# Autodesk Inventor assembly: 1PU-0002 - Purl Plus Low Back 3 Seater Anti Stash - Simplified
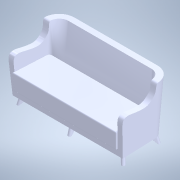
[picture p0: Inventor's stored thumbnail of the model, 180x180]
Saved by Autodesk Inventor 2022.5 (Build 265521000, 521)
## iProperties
Created: 2025-09
Part Number: 1PU-0002 - Purl Plus Low Back 3 Seater Anti Stash - Simplified
Description: STEP AP214
Document SubType Name: Assembly
Designer: Mark.Glazzard
Title: 1PU-0002 - Purl Plus Low Back 3 Seater Anti Stash (Upholstered).STEP
Revision Number: ANY
Sending System: SolidWorks 2025
Preprocessor: SwSTEP 2.0
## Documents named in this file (5)
- S:\DRAWINGS\DRAWING OFFICE ONLY\WIP\1306 Purl 3-Seater\1PU-0002 - Purl Plus Low Back Anti Stash 3 Seater\1PU-0002 SIMPLIFIED\1PU-0002 - Purl Plus Low Back 3 Seater Anti Stash - Simplified.iam
- S:\DRAWINGS\DRAWING OFFICE ONLY\WIP\1306 Purl 3-Seater\1PU-0002 - Purl Plus Low Back Anti Stash 3 Seater\1PU-0002 STEP SAT DWG\1PU-0002 - BEECH FEET.ipt
- S:\DRAWINGS\DRAWING OFFICE ONLY\WIP\1306 Purl 3-Seater\1PU-0002 - Purl Plus Low Back Anti Stash 3 Seater\1PU-0002 STEP SAT DWG\1PU-0002 - FR BLACK LINING FABRIC - 2SEATER.ipt
- S:\DRAWINGS\DRAWING OFFICE ONLY\WIP\1306 Purl 3-Seater\1PU-0002 - Purl Plus Low Back Anti Stash 3 Seater\1PU-0002 STEP SAT DWG\1PU-0002 - Upholstery 2.ipt
- S:\DRAWINGS\DRAWING OFFICE ONLY\WIP\1306 Purl 3-Seater\1PU-0002 - Purl Plus Low Back Anti Stash 3 Seater\1PU-0002 STEP SAT DWG\1PU-0002 - Upholstery 1.ipt
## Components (9 placed, 9 different names)
1. 1PU-0002 - BEECH FEET_1
2. 1PU-0002 - BEECH FEET_2
3. 1PU-0002 - BEECH FEET_3
4. 1PU-0002 - BEECH FEET_4
5. 1PU-0002 - FR BLACK LINING FABRIC - 2SEATER_5
6. 1PU-0002 - Upholstery 2_6
7. 1PU-0002 - Upholstery 1_7
8. 1PU-0002 - BEECH FEET_8
9. 1PU-0002 - BEECH FEET_9
